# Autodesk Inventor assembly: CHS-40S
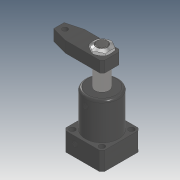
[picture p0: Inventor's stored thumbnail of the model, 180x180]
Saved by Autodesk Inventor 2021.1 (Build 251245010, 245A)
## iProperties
Created: 2019-04
Part Number: CHS-40S
Description: STEP AP203
Document SubType Name: Assembly
Designer: user
Sending System: SolidWorks 2017
Preprocessor: SwSTEP 2.0
Title: chs-40s_asm.STEP
Revision Number: ÈÎºÎ
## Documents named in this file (5)
- D:\Vault_2016\Projekty\Clamptek\Hydraulic\CHS\CHS-40\Inventor\CHS-40S\CHS-40S.iam
- D:\Vault_2016\Projekty\Clamptek\Hydraulic\CHS\CHS-40\Inventor\CHS-40S\CHS-40-03_1.ipt
- D:\Vault_2016\Projekty\Clamptek\Hydraulic\CHS\CHS-40\Inventor\CHS-40S\CHS-40S-02.ipt
- D:\Vault_2016\Projekty\Clamptek\Hydraulic\CHS\CHS-40\Inventor\CHS-40S\CHS-40S-01.ipt
- D:\Vault_2016\Projekty\Clamptek\Hydraulic\CHS\CHS-40\Inventor\CHS-40S\M18.ipt
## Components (4 placed, 4 different names)
1. CHS-40-03_1_1
2. CHS-40S-02_2
3. CHS-40S-01_3
4. M18_4
